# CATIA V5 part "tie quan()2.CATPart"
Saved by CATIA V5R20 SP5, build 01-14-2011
Part number: 外框2
Bounding box of the stored display mesh (mm): x -152.63 to 152.63, y -152.63 to 152.63, z -0.505 to 111
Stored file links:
  E:\姜浩然03.08\创意作品\tie quan()2.CATPart
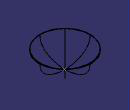
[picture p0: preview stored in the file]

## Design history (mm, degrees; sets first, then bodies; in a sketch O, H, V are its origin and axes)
Body1 (main body)
  Sketch1 on xy-plane, origin (0, 0, 0), H (1, 0, 0), V (0, 1, 0)
    circle A1 centre (0, 0) radius 5
  Pad1: profile Sketch1, direction (0, 0, 1), length 0.5, mirrored extent
  Plane1: type Offset, RefPlane zx-plane, Offset 5, reversed
  Point1: type OnPlane, Support Plane1, H 0, V 0, Direction (-1, 0, 0)
  Circle1: type CtrRad, Start 0, End 180, Center Point1, Support Plane1, Radius 0.5, FirstDirection (-1, 0, 0)
  Sketch2 on yz-plane, origin (0, 0, 0), H (0, 1, 0), V (0, 0, 1)
    spline S1 through (-4.955, 0) (-152.1268, 105.2207) (-152.1268, 109.4858)
    point P1 (-4.955, 0)
    coincidence: P1 H
  Rib1: profile Circle1, centre curve Sketch2
  CircPattern1: of the body so far, instances 8, angular step 45, axis from end face of Pad1
Body2
  Plane2: type Offset, RefPlane xy-plane, Offset 110
  Sketch3 on Plane2, origin (0, 0, 110), H (1, 0, 0), V (0, 1, 0)
    circle A1 centre (0, 0) radius 151.634
  Pad2: profile Sketch3, direction (0, 0, 1), length 1, mirrored extent
  Sketch4 on end face of Pad2, origin (0, 0, 111), H (1, 0, 0), V (0, 1, 0)
    point P1 (0, 0)
  Hole1: placed by Sketch4, at (0, 0, 111) direction (0, 0, -1), diameter 300, through (limit type 6)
